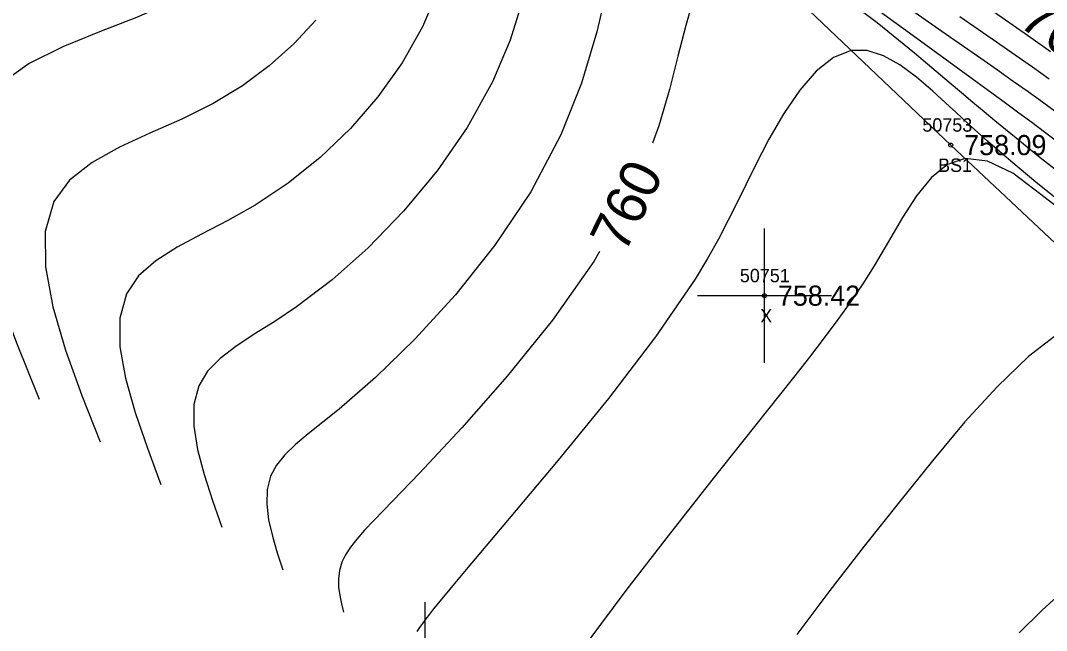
# Model space of a CAD drawing. Extents: x 1378535 to 1380697, y 997729 to 1000024.
# Drawn here: x 1378818.4 to 1378894.9, y 999583.9 to 999629.4 of the extents above; entities that cross this region are included whole.
import ezdxf

# ---------------------------------------------------------------- set-up
doc = ezdxf.new("R2010")
doc.units = 0
for name, color, linetype in [('RD_DTM_BkLn2', 7, 'Continuous'), ('RD_DTM_BkLn_txCode', 7, 'Continuous'), ('RD_DTM_Major1', 7, 'Continuous'), ('RD_DTM_Major1_Lbl', 7, 'Continuous'), ('RD_DTM_Minor1', 7, 'Continuous'), ('RD_EX_Misc', 7, 'Continuous'), ('RD_EX_Misc_txCode', 7, 'Continuous'), ('RD_EX_TX_Misc_ELEV', 7, 'Continuous'), ('RD_SMD_Locator', 7, 'Continuous')]:
    doc.layers.add(name, color=color, linetype=linetype)

msp = doc.modelspace()

# ---------------------------------------------------------------- linework, layer by layer
at = {"layer": 'RD_DTM_BkLn2'}
msp.add_lwpolyline([(1379120.522, 999436.728), (1379105.901, 999448.958), (1379055.44, 999473.982), (1379013.575, 999506.052), (1378969.754, 999549.783), (1378921.742, 999588.169), (1378887.745, 999620.093), (1378838.962, 999666.497), (1378808.003, 999710.025), (1378787.76, 999741.475)], dxfattribs=at)
at = {"layer": 'RD_DTM_Major1'}
for points in [[(1378834.037, 999633.608), (1378833.043, 999632.79), (1378831.446, 999631.719), (1378829.66, 999630.745), (1378827.031, 999629.6), (1378824.256, 999628.531), (1378821.52, 999627.427), (1378819.011, 999626.178), (1378816.913, 999624.672), (1378815.414, 999622.797), (1378814.599, 999620.129), (1378814.625, 999616.948), (1378815.322, 999613.355), (1378816.523, 999609.455), (1378818.06, 999605.348), (1378819.765, 999601.139)], [(1378896.265, 999617.697), (1378894.422, 999619.151), (1378892.623, 999620.6), (1378891.831, 999621.249), (1378891.035, 999621.907), (1378890.227, 999622.58), (1378889.397, 999623.276), (1378888.537, 999624.002), (1378887.637, 999624.763), (1378885.045, 999626.948), (1378882.262, 999629.218), (1378879.437, 999631.36)], [(1378868.566, 999631.014), (1378867.977, 999629.007), (1378867.401, 999626.732), (1378866.759, 999624.229), (1378865.972, 999621.541), (1378865.503, 999620.226)], [(1378861.559, 999612.161), (1378861.119, 999611.401), (1378858.039, 999607.048), (1378854.673, 999602.868), (1378851.281, 999599.011), (1378848.125, 999595.629), (1378845.466, 999592.873), (1378844.7, 999592.079), (1378844.028, 999591.366), (1378843.454, 999590.715), (1378842.978, 999590.113), (1378842.604, 999589.543), (1378842.333, 999588.989), (1378842.148, 999588.365), (1378842.076, 999587.742), (1378842.094, 999587.119), (1378842.18, 999586.496), (1378842.31, 999585.874), (1378842.463, 999585.252)]]:
    msp.add_lwpolyline(points, dxfattribs=at)
at = {"layer": 'RD_DTM_Minor1'}
for points in [[(1378862.193, 999632.191), (1378861.359, 999628.53), (1378860.208, 999624.7), (1378858.674, 999620.851), (1378856.416, 999616.615), (1378853.737, 999612.62), (1378850.804, 999608.933), (1378847.78, 999605.621), (1378844.832, 999602.751), (1378842.125, 999600.39), (1378840.919, 999599.419), (1378839.832, 999598.553), (1378838.881, 999597.755), (1378838.083, 999596.99), (1378837.457, 999596.219), (1378837.021, 999595.406), (1378836.765, 999594.398), (1378836.731, 999593.306), (1378836.874, 999592.146), (1378837.15, 999590.935), (1378837.515, 999589.691), (1378837.924, 999588.429)], [(1378849.4, 999631.379), (1378848.355, 999628.922), (1378846.842, 999626.234), (1378845.029, 999623.692), (1378842.971, 999621.325), (1378840.722, 999619.167), (1378838.336, 999617.248), (1378835.867, 999615.601), (1378833.84, 999614.465), (1378831.875, 999613.45), (1378830.054, 999612.477), (1378828.458, 999611.464), (1378827.167, 999610.332), (1378826.264, 999609.001), (1378825.775, 999607.18), (1378825.787, 999605.06), (1378826.2, 999602.7), (1378826.914, 999600.161), (1378827.829, 999597.503), (1378828.844, 999594.784)], [(1378855.854, 999631.052), (1378854.879, 999627.909), (1378853.572, 999624.811), (1378851.679, 999621.4), (1378849.435, 999618.167), (1378846.941, 999615.162), (1378844.297, 999612.437), (1378841.603, 999610.043), (1378838.958, 999608.03), (1378837.326, 999606.945), (1378835.801, 999605.981), (1378834.428, 999605.079), (1378833.251, 999604.179), (1378832.314, 999603.222), (1378831.663, 999602.149), (1378831.303, 999600.738), (1378831.296, 999599.138), (1378831.571, 999597.387), (1378832.058, 999595.523), (1378832.685, 999593.584), (1378833.384, 999591.607)], [(1378896.432, 999619.79), (1378894.741, 999621.057), (1378893.788, 999621.766), (1378892.824, 999622.478), (1378891.833, 999623.208), (1378890.798, 999623.966), (1378889.703, 999624.767), (1378888.53, 999625.622), (1378885.206, 999628.04), (1378881.521, 999630.716)], [(1378895.637, 999622.521), (1378894.587, 999623.284), (1378893.516, 999624.054), (1378892.405, 999624.845), (1378891.235, 999625.671), (1378889.986, 999626.546), (1378887.066, 999628.576), (1378883.838, 999630.815)], [(1378895.183, 999627.04), (1378893.71, 999628.09), (1378892.151, 999629.196), (1378889.469, 999631.085)], [(1378895.078, 999625.014), (1378893.841, 999625.893), (1378892.544, 999626.805), (1378891.166, 999627.764), (1378888.432, 999629.653)], [(1378840.389, 999629.42), (1378838.752, 999627.64), (1378836.922, 999625.995), (1378834.914, 999624.507), (1378832.746, 999623.194), (1378830.39, 999622.031), (1378828.012, 999620.977), (1378825.74, 999619.934), (1378823.702, 999618.804), (1378822.027, 999617.489), (1378820.843, 999615.89), (1378820.204, 999613.65), (1378820.229, 999611.002), (1378820.783, 999608.028), (1378821.736, 999604.808), (1378822.954, 999601.426), (1378824.304, 999597.962)], [(1378896.09, 999615.714), (1378894.085, 999617.331), (1378892.214, 999618.886), (1378890.482, 999620.387), (1378889.993, 999620.824), (1378889.514, 999621.259), (1378889.043, 999621.69), (1378888.115, 999622.549), (1378887.652, 999622.978), (1378886.419, 999624.107), (1378885.18, 999625.164), (1378883.943, 999626.074), (1378882.716, 999626.76), (1378881.506, 999627.145), (1378880.321, 999627.155), (1378878.992, 999626.634), (1378877.71, 999625.609), (1378876.479, 999624.183), (1378875.301, 999622.454), (1378874.182, 999620.525), (1378873.124, 999618.494), (1378872.476, 999617.18), (1378871.827, 999615.851), (1378871.15, 999614.492), (1378870.418, 999613.089), (1378869.602, 999611.627), (1378868.675, 999610.09), (1378865.732, 999605.794), (1378862.216, 999601.198), (1378858.464, 999596.586), (1378854.814, 999592.242), (1378851.603, 999588.451), (1378849.168, 999585.499), (1378848.863, 999585.11), (1378848.588, 999584.751), (1378848.34, 999584.417), (1378848.118, 999584.108), (1378847.922, 999583.821)], [(1378896.621, 999614.755), (1378894.458, 999616.405), (1378892.362, 999618.006), (1378890.485, 999618.898), (1378888.811, 999619.092), (1378887.49, 999618.637), (1378886.297, 999617.674), (1378885.193, 999616.32), (1378884.14, 999614.694), (1378883.099, 999612.913), (1378882.033, 999611.096), (1378881.184, 999609.752), (1378880.288, 999608.427), (1378879.333, 999607.094), (1378878.308, 999605.724), (1378877.202, 999604.289), (1378876.005, 999602.763), (1378873.108, 999599.105), (1378869.929, 999595.097), (1378866.668, 999590.95), (1378863.522, 999586.873), (1378860.689, 999583.074)], [(1378895.812, 999606.059), (1378893.538, 999604.318), (1378891.197, 999602.076), (1378888.803, 999599.446), (1378886.372, 999596.546), (1378883.916, 999593.492), (1378881.297, 999590.182), (1378878.725, 999586.87), (1378876.256, 999583.599)], [(1378896.294, 999586.992), (1378894.544, 999585.388), (1378892.852, 999583.723)]]:
    msp.add_lwpolyline(points, dxfattribs=at)
at = {"layer": 'RD_EX_Misc'}
for p, q in [((1378873.851, 999603.864), (1378873.851, 999613.864)), ((1378868.851, 999608.864), (1378878.851, 999608.864)), ((1378848.542, 999575.997), (1378848.542, 999585.997))]:
    msp.add_line(p, q, dxfattribs=at)
at = {"layer": 'RD_SMD_Locator'}
for centre in [(1378887.745, 999620.093), (1378873.851, 999608.864)]:
    msp.add_circle(centre, 0.15, dxfattribs=at)

# ---------------------------------------------------------------- texts
at = {"layer": 'RD_DTM_BkLn_txCode'}
for s, p in [('50753', (1378885.627, 999621.093)), ('BS1', (1378886.8, 999618.093))]:
    msp.add_text(s, height=1, dxfattribs=at).set_placement(p)
at = {"layer": 'RD_DTM_Major1_Lbl'}
for s, rotation, p in [('765', 324.34386, (1378892.676, 999629.069)), ('760', 63.93917, (1378863.429, 999611.932))]:
    msp.add_text(s, height=3, rotation=rotation, dxfattribs=at).set_placement(p)
at = {"layer": 'RD_EX_Misc_txCode'}
for s, p in [('50751', (1378872.016, 999609.864)), ('X', (1378873.536, 999606.864))]:
    msp.add_text(s, height=1, dxfattribs=at).set_placement(p)
at = {"layer": 'RD_EX_TX_Misc_ELEV'}
for s, p in [('758.09', (1378888.745, 999619.343)), ('758.42', (1378874.851, 999608.114))]:
    msp.add_text(s, height=1.5, dxfattribs=at).set_placement(p)

doc.saveas('drawing.dxf')
